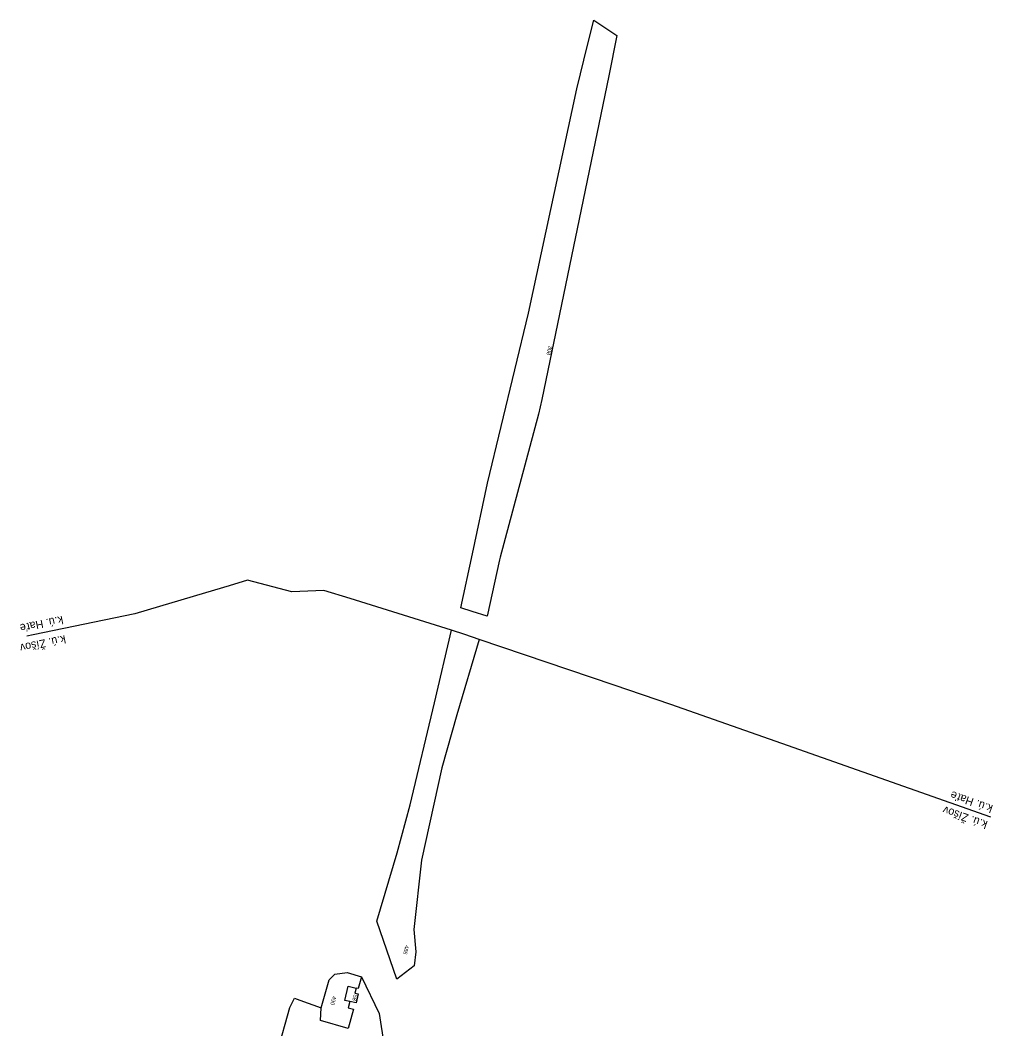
# Model space of a CAD drawing. Extents: x -700390 to -699853, y -1069116 to -1066813.
# Drawn here: x -700240.8 to -699876.4, y -1068173.9 to -1067795.7 of the extents above; entities that cross this region are included whole.
import ezdxf

# ---------------------------------------------------------------- set-up
doc = ezdxf.new("R2010")
doc.units = 0
for name, color, linetype in [('Vrstva 53', 7, 'Continuous'), ('Vrstva 55', 7, 'Continuous'), ('Vrstva 57', 7, 'Continuous')]:
    doc.layers.add(name, color=color, linetype=linetype)

msp = doc.modelspace()

# ---------------------------------------------------------------- linework, layer by layer
at = {"layer": 'Vrstva 53'}
for points in [[(-700075.75, -1068016.05), (-700071.34, -1067995.75), (-700065.73, -1067969.32), (-700050.29, -1067905.52), (-700032.26, -1067821.43), (-700028.18, -1067805.03), (-700025.86, -1067795.71)], [(-700025.86, -1067795.71), (-700020.96, -1067799.01), (-700017.25, -1067801.5), (-700020.29, -1067816.64), (-700045.39, -1067937.94), (-700046.59, -1067943.42), (-700060.95, -1067997.01), (-700061.16, -1067997.98), (-700065.86, -1068019.21), (-700071.47, -1068017.42), (-700075.75, -1068016.05)], [(-700099.66, -1068155.28), (-700107.22, -1068133.46), (-700099.51, -1068107.86), (-700094.74, -1068089.83), (-700085.54, -1068051.67), (-700079.26, -1068024.45)], [(-700068.77, -1068027.88), (-700074.2, -1068026.04), (-700079.26, -1068024.45)], [(-700068.77, -1068027.88), (-700077.24, -1068056.21), (-700082.81, -1068076.08), (-700090.39, -1068110.64), (-700093.29, -1068136.63), (-700092.59, -1068145.04), (-700093.15, -1068150.31), (-700099.66, -1068155.28)], [(-700139.57, -1068349.33), (-700140.37, -1068347.45), (-700154.33, -1068314.6), (-700127.48, -1068216.62), (-700150.86, -1068210.98), (-700147.46, -1068195.84), (-700144.44, -1068182.36), (-700139.73, -1068165.83), (-700138.06, -1068162.39), (-700136.01, -1068163.13), (-700128, -1068166.03), (-700125, -1068155.45), (-700122.97, -1068153.33), (-700118.3, -1068152.8), (-700112.98, -1068154.39)], [(-700112.98, -1068154.39), (-700106.34, -1068168.15), (-700100.69, -1068204.52), (-700095.19, -1068243.17), (-700097.88, -1068242.45), (-700122.52, -1068345.31), (-700127.75, -1068351.76), (-700139.55, -1068349.38), (-700139.57, -1068349.33)]]:
    msp.add_lwpolyline(points, dxfattribs=at)
at = {"layer": 'Vrstva 55'}
for points in [[(-700079.26, -1068024.45), (-700117.11, -1068012.59), (-700127.01, -1068009.49), (-700138.99, -1068009.98), (-700155.68, -1068005.71), (-700162.55, -1068007.76), (-700171.36, -1068010.39), (-700197.86, -1068018.31), (-700235.97, -1068026.12), (-700238.38, -1068026.61)], [(-699877.11, -1068094.51), (-699955.42, -1068066.88), (-699996.96, -1068052.22), (-700018.24, -1068045.01), (-700068.77, -1068027.88), (-700074.2, -1068026.04), (-700079.26, -1068024.45)], [(-700112.98, -1068154.39), (-700114.18, -1068158.74), (-700114.95, -1068158.59)], [(-700117.27, -1068163.61), (-700119.15, -1068163.19), (-700117.98, -1068157.92), (-700114.95, -1068158.59)], [(-700114.95, -1068158.59), (-700115.39, -1068160.55), (-700114.22, -1068160.81), (-700114.95, -1068164.12), (-700117.27, -1068163.61)], [(-700117.27, -1068163.61), (-700117.88, -1068165.99), (-700115.96, -1068166.48), (-700117.86, -1068173.7), (-700128.35, -1068170.7), (-700128, -1068166.03)]]:
    msp.add_lwpolyline(points, dxfattribs=at)

# ---------------------------------------------------------------- texts
for s, rotation, p in [('k.ú. Haťe', 191.5814, (-700225.05, -1068018.98)), ('k.ú. Žíšov', 191.5814, (-700224.09, -1068026.23)), ('k.ú. Haťe', 160.5657, (-699876.1, -1068090.12)), ('k.ú. Žíšov', 160.5657, (-699878.07, -1068096.09))]:
    msp.add_text(s, height=3, rotation=rotation, dxfattribs=at).set_placement(p)
at = {"layer": 'Vrstva 57'}
for s, rotation, p in [('308', 256.4157, (-700042.8, -1067917.7)), ('486', 256.3756, (-700096.54, -1068142.44)), ('490', 256.4578, (-700123.8, -1068161.45)), ('58', 256.4578, (-700115.85, -1068160.94))]:
    msp.add_text(s, height=1.5, rotation=rotation, dxfattribs=at).set_placement(p)

doc.saveas('drawing.dxf')
